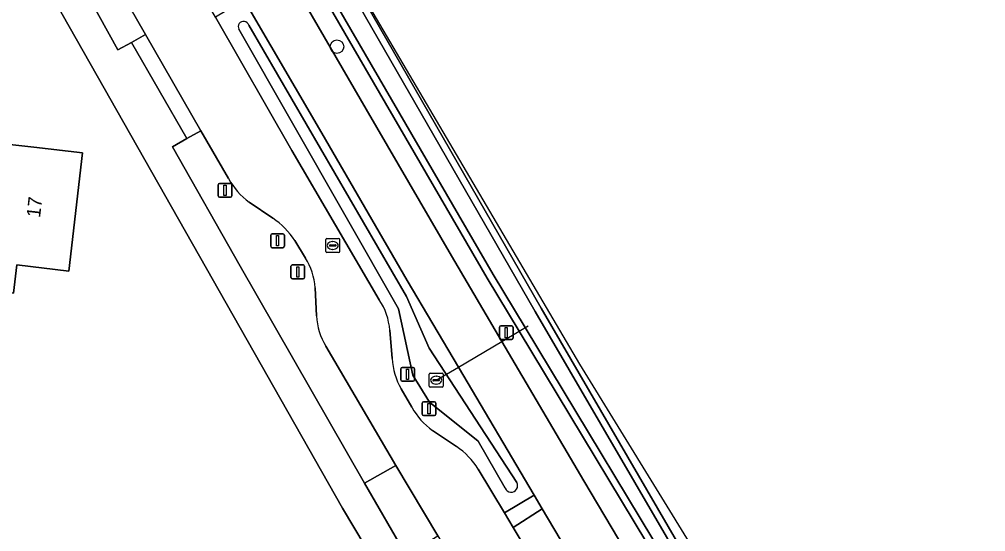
# Model space of a CAD drawing. Extents: x 162396 to 163643, y 386452 to 387406.
# Drawn here: x 163078.6 to 163148.6, y 386894 to 386931.2 of the extents above; entities that cross this region are included whole.
import ezdxf

# ---------------------------------------------------------------- set-up
doc = ezdxf.new("R2010")
doc.units = 0
for name, color, linetype in [('IMGEO_Afsluitpaal', 7, 'Continuous'), ('IMGEO_Berm_groen', 7, 'Continuous'), ('IMGEO_Boom', 7, 'Continuous'), ('IMGEO_Duiker', 7, 'Continuous'), ('IMGEO_Erf', 7, 'Continuous'), ('IMGEO_Fietspad_gesloten', 7, 'Continuous'), ('IMGEO_Fietspad_halfverhard', 7, 'Continuous'), ('IMGEO_Grasland_agrarisch', 7, 'Continuous'), ('IMGEO_Greppel_droge_sloot', 7, 'Continuous'), ('IMGEO_Hek', 7, 'Continuous'), ('IMGEO_Lichtmast', 7, 'Continuous'), ('IMGEO_Oever', 7, 'Continuous'), ('IMGEO_Pand', 7, 'Continuous'), ('IMGEO_Pand_nummerreeks', 7, 'Continuous'), ('IMGEO_Parkeervlak_halfverhard', 7, 'Continuous'), ('IMGEO_Rijbaan_lokaal_gesloten', 7, 'Continuous'), ('IMGEO_Rioolput', 7, 'Continuous'), ('IMGEO_Voetpad_open', 7, 'Continuous')]:
    doc.layers.add(name, color=color, linetype=linetype)

msp = doc.modelspace()

# ---------------------------------------------------------------- linework, layer by layer
at = {"layer": 'IMGEO_Afsluitpaal'}
for p, q in [((163096.799, 386914.692), (163096.799, 386915.492)), ((163096.799, 386915.492), (163096.799, 386914.692)), ((163096.899, 386915.592), (163097.689, 386915.592)), ((163097.689, 386915.592), (163096.899, 386915.592)), ((163097.789, 386915.492), (163097.789, 386914.692)), ((163097.789, 386914.692), (163097.789, 386915.492)), ((163097.689, 386914.592), (163096.899, 386914.592)), ((163096.899, 386914.592), (163097.689, 386914.592)), ((163098.369, 386913.338), (163099.159, 386913.338)), ((163099.159, 386913.338), (163098.369, 386913.338)), ((163098.269, 386912.438), (163098.269, 386913.238)), ((163098.269, 386913.238), (163098.269, 386912.438)), ((163099.259, 386913.238), (163099.259, 386912.438)), ((163099.259, 386912.438), (163099.259, 386913.238)), ((163099.159, 386912.338), (163098.369, 386912.338)), ((163098.369, 386912.338), (163099.159, 386912.338)), ((163106.225, 386905.008), (163106.225, 386905.808)), ((163106.225, 386905.808), (163106.225, 386905.008)), ((163106.325, 386905.908), (163107.115, 386905.908)), ((163107.115, 386905.908), (163106.325, 386905.908)), ((163107.215, 386905.808), (163107.215, 386905.008)), ((163107.215, 386905.008), (163107.215, 386905.808)), ((163107.115, 386904.908), (163106.325, 386904.908)), ((163106.325, 386904.908), (163107.115, 386904.908)), ((163107.777, 386902.512), (163107.777, 386903.312)), ((163107.777, 386903.312), (163107.777, 386902.512)), ((163107.877, 386903.412), (163108.667, 386903.412)), ((163108.667, 386903.412), (163107.877, 386903.412)), ((163108.767, 386903.312), (163108.767, 386902.512)), ((163108.767, 386902.512), (163108.767, 386903.312)), ((163108.667, 386902.412), (163107.877, 386902.412)), ((163107.877, 386902.412), (163108.667, 386902.412))]:
    msp.add_line(p, q, dxfattribs=at)
for points in [[(163097.219, 386915.467), (163097.369, 386915.467), (163097.369, 386914.717), (163097.219, 386914.717), (163097.219, 386915.467)], [(163098.689, 386913.213), (163098.839, 386913.213), (163098.839, 386912.463), (163098.689, 386912.463), (163098.689, 386913.213)], [(163106.645, 386905.783), (163106.795, 386905.783), (163106.795, 386905.033), (163106.645, 386905.033), (163106.645, 386905.783)], [(163108.197, 386903.287), (163108.347, 386903.287), (163108.347, 386902.537), (163108.197, 386902.537), (163108.197, 386903.287)]]:
    msp.add_lwpolyline(points, dxfattribs=at)
for centre, start, end in [((163096.899, 386915.492), 90, 180), ((163096.899, 386915.492), 90, 180), ((163097.689, 386915.492), 0, 90), ((163097.689, 386915.492), 360, 90), ((163096.899, 386914.692), 180, 270), ((163096.899, 386914.692), 180, 270), ((163097.689, 386914.692), 270, 0), ((163097.689, 386914.692), 270, 0), ((163098.369, 386913.238), 90, 180), ((163098.369, 386913.238), 90, 180), ((163099.159, 386913.238), 0, 90), ((163099.159, 386913.238), 360, 90), ((163098.369, 386912.438), 180, 270), ((163098.369, 386912.438), 180, 270), ((163099.159, 386912.438), 270, 0), ((163099.159, 386912.438), 270, 0), ((163106.325, 386905.808), 90, 180), ((163106.325, 386905.808), 90, 180), ((163107.115, 386905.808), 0, 90), ((163107.115, 386905.808), 360, 90), ((163106.325, 386905.008), 180, 270), ((163106.325, 386905.008), 180, 270), ((163107.115, 386905.008), 270, 0), ((163107.115, 386905.008), 270, 0), ((163107.877, 386903.312), 90, 180), ((163107.877, 386903.312), 90, 180), ((163108.667, 386903.312), 0, 90), ((163108.667, 386903.312), 360, 90), ((163107.877, 386902.512), 180, 270), ((163107.877, 386902.512), 180, 270), ((163108.667, 386902.512), 270, 0), ((163108.667, 386902.512), 270, 0)]:
    msp.add_arc(centre, 0.1, start, end, dxfattribs=at)
at = {"layer": 'IMGEO_Berm_groen'}
for points in [[(163058.321, 387013.033), (163062.245, 387003.85), (163065.679, 386996.007), (163072.387, 386981.888), (163076.252, 386973.982), (163079.946, 386966.717), (163082.017, 386962.946), (163085.197, 386957.174), (163087.753, 386952.543), (163088.198, 386951.737), (163088.644, 386950.931), (163089.035, 386950.226), (163090.045, 386948.352), (163091.713, 386945.359), (163103.715, 386924.646), (163109.912, 386913.996), (163113.552, 386907.796), (163119.49, 386897.68), (163133.047, 386874.854), (163141.068, 386861.652), (163143.895, 386857.051), (163155.065, 386838.871)], [(163153.066, 386846.995), (163145.801, 386858.335), (163140.584, 386866.478), (163126.817, 386888.603), (163114.805, 386908.538), (163112.488, 386912.383), (163096.88, 386939.306)], [(163100.492, 386922.911), (163094.886, 386932.55), (163092.789, 386931.308), (163098.32, 386921.635), (163104.671, 386910.799)], [(163113.792, 386897.146), (163111.823, 386900.546), (163108.303, 386903.381), (163107.11, 386905.349), (163106.066, 386910.153), (163094.49, 386930.439)], [(163095.206, 386930.737), (163106.632, 386911.047), (163108.273, 386907.289), (163114.627, 386897.563)], [(163091.734, 386923.078), (163090.714, 386922.504), (163089.68, 386921.904), (163094.586, 386913.257), (163103.597, 386897.495), (163105.855, 386898.787), (163100.8, 386907.449)], [(163093.731, 386919.599), (163091.734, 386923.078)], [(163111.839, 386898.512), (163113.745, 386895.358), (163115.894, 386896.629), (163110.406, 386905.934), (163106.699, 386912.218), (163100.492, 386922.911)], [(163096.944, 386916.735), (163095.24, 386917.884)], [(163099.312, 386913.838), (163098.54, 386915.109)], [(163100.117, 386909.636), (163100.03, 386911.687)], [(163105.438, 386908.608), (163105.611, 386906.545)], [(163106.246, 386904.35), (163107.019, 386903.009)], [(163108.535, 386901.325), (163110.255, 386900.168)]]:
    msp.add_lwpolyline(points, dxfattribs=at)
for points in [[(163084.761, 386935.248), (163082.833, 386934.162), (163085.725, 386928.948), (163086.703, 386929.474), (163087.725, 386930.063)], [(163116.481, 386895.637), (163114.367, 386894.296), (163127.83, 386871.73), (163134.797, 386860.218), (163136.893, 386861.494), (163129.911, 386872.986)]]:
    msp.add_lwpolyline(points, close=True, dxfattribs=at)
for centre, radius, start, end in [((163094.834, 386930.621), 0.389, 17.32456, 207.8697), ((163098.71, 386922.459), 5.742, 209.87088, 232.81715), ((163094.064, 386912.312), 5.278, 32.00171, 56.93136), ((163095.268, 386911.293), 4.779, 4.73337, 32.18447), ((163100.627, 386908.154), 4.832, 5.39554, 33.19154), ((163104.77, 386909.889), 4.66, 183.11311, 211.57406), ((163110.677, 386906.821), 5.073, 183.12072, 209.14895), ((163111.657, 386905.66), 5.342, 209.75077, 234.23869), ((163107.412, 386895.863), 5.159, 30.89421, 56.55973), ((163114.227, 386897.32), 0.468, 201.78194, 31.29325)]:
    msp.add_arc(centre, radius, start, end, dxfattribs=at)
at = {"layer": 'IMGEO_Boom'}
msp.add_circle((163101.599, 386929.174), 0.489, dxfattribs=at)
at = {"layer": 'IMGEO_Duiker'}
msp.add_lwpolyline([(163108.792, 386904.978), (163110.406, 386905.934), (163113.552, 386907.796), (163114.805, 386908.538), (163115.453, 386908.922)], dxfattribs=at)
at = {"layer": 'IMGEO_Erf'}
msp.add_lwpolyline([(163143.068, 386827.803), (163123.585, 386859.49), (163102.006, 386895.698), (163079.761, 386934.958), (163074.122, 386945.175)], dxfattribs=at)
msp.add_lwpolyline([(163066.997, 386929.103), (163070.741, 386928.672), (163075.708, 386928.1), (163075.247, 386924.097), (163075.052, 386922.399), (163079.622, 386921.873), (163083.162, 386921.466), (163082.176, 386912.899), (163078.39, 386913.335), (163078.154, 386911.287), (163073.187, 386911.859), (163069.581, 386912.274), (163070.781, 386922.707), (163066.32, 386923.22)], close=True, dxfattribs=at)
at = {"layer": 'IMGEO_Fietspad_gesloten'}
for points in [[(163155.065, 386838.871), (163143.895, 386857.051), (163141.068, 386861.652), (163133.047, 386874.854), (163119.49, 386897.68), (163113.552, 386907.796), (163109.912, 386913.996), (163103.715, 386924.646), (163091.713, 386945.359), (163090.045, 386948.352), (163089.035, 386950.226), (163088.644, 386950.931), (163088.198, 386951.737), (163087.753, 386952.543), (163085.197, 386957.174), (163082.017, 386962.946), (163079.946, 386966.717), (163076.252, 386973.982), (163072.387, 386981.888), (163065.679, 386996.007), (163062.245, 387003.85), (163058.321, 387013.033)], [(163081.061, 386957.239), (163084.489, 386950.829), (163086.516, 386947.047), (163094.302, 386933.576), (163094.886, 386932.55), (163100.492, 386922.911), (163106.699, 386912.218), (163110.406, 386905.934), (163115.894, 386896.629), (163116.481, 386895.637), (163129.911, 386872.986), (163136.893, 386861.494), (163137.525, 386860.5), (163140.88, 386855.017), (163151.706, 386837.322), (163156.522, 386829.586)]]:
    msp.add_lwpolyline(points, dxfattribs=at)
at = {"layer": 'IMGEO_Fietspad_halfverhard'}
msp.add_lwpolyline([(163116.481, 386895.637), (163115.894, 386896.629), (163113.745, 386895.358), (163114.367, 386894.296)], close=True, dxfattribs=at)
at = {"layer": 'IMGEO_Grasland_agrarisch'}
msp.add_lwpolyline([(163098.137, 386941.992), (163116.399, 386910.212), (163128.365, 386889.63), (163142.301, 386867.412), (163154.565, 386848.11), (163157.583, 386842.961), (163157.905, 386843.143), (163162.006, 386845.923), (163174.171, 386826.377), (163170.355, 386823.925), (163171.995, 386820.854), (163236.272, 386723.927)], dxfattribs=at)
at = {"layer": 'IMGEO_Greppel_droge_sloot'}
for points in [[(163097.315, 386939.553), (163112.918, 386912.637), (163115.235, 386908.793), (163127.243, 386888.864), (163141.007, 386866.745), (163146.215, 386858.615), (163153.49, 386847.26), (163159.708, 386837.054), (163160.184, 386837.158), (163160.318, 386837.307), (163157.295, 386842.465), (163157.152, 386842.708), (163154.138, 386847.849), (163141.878, 386867.145), (163127.937, 386889.371), (163115.966, 386909.962), (163097.705, 386941.74)], [(163094.49, 386930.439), (163106.066, 386910.153), (163107.11, 386905.349), (163108.303, 386903.381), (163111.823, 386900.546), (163113.792, 386897.146)], [(163108.273, 386907.289), (163106.632, 386911.047), (163095.206, 386930.737)], [(163114.627, 386897.563), (163108.273, 386907.289)]]:
    msp.add_lwpolyline(points, dxfattribs=at)
for centre, radius, start, end in [((163094.834, 386930.621), 0.389, 17.32456, 207.8697), ((163114.227, 386897.32), 0.468, 201.78194, 31.29325)]:
    msp.add_arc(centre, radius, start, end, dxfattribs=at)
at = {"layer": 'IMGEO_Hek'}
for points in [[(163119.211, 386906.146), (163099.887, 386939.051), (163083.129, 386969.417), (163073.808, 386988.989), (163068.186, 387000), (163054.818, 387033.276)], [(163157.905, 386843.143), (163119.211, 386906.146)]]:
    msp.add_lwpolyline(points, dxfattribs=at)
at = {"layer": 'IMGEO_Lichtmast'}
for p, q in [((163092.991, 386918.346), (163092.991, 386919.146)), ((163092.991, 386919.146), (163092.991, 386918.346)), ((163093.091, 386919.246), (163093.881, 386919.246)), ((163093.881, 386919.246), (163093.091, 386919.246)), ((163093.981, 386919.146), (163093.981, 386918.346)), ((163093.981, 386918.346), (163093.981, 386919.146)), ((163093.881, 386918.246), (163093.091, 386918.246)), ((163093.091, 386918.246), (163093.881, 386918.246)), ((163113.373, 386908.023), (163113.373, 386908.823)), ((163113.373, 386908.823), (163113.373, 386908.023)), ((163113.473, 386908.923), (163114.263, 386908.923)), ((163114.263, 386908.923), (163113.473, 386908.923)), ((163114.363, 386908.823), (163114.363, 386908.023)), ((163114.363, 386908.023), (163114.363, 386908.823)), ((163114.263, 386907.923), (163113.473, 386907.923)), ((163113.473, 386907.923), (163114.263, 386907.923))]:
    msp.add_line(p, q, dxfattribs=at)
for points in [[(163093.411, 386919.121), (163093.561, 386919.121), (163093.561, 386918.371), (163093.411, 386918.371), (163093.411, 386919.121)], [(163113.793, 386908.798), (163113.943, 386908.798), (163113.943, 386908.048), (163113.793, 386908.048), (163113.793, 386908.798)]]:
    msp.add_lwpolyline(points, dxfattribs=at)
for centre, start, end in [((163093.091, 386919.146), 90, 180), ((163093.091, 386919.146), 90, 180), ((163093.881, 386919.146), 0, 90), ((163093.881, 386919.146), 360, 90), ((163093.091, 386918.346), 180, 270), ((163093.091, 386918.346), 180, 270), ((163093.881, 386918.346), 270, 0), ((163093.881, 386918.346), 270, 0), ((163113.473, 386908.823), 90, 180), ((163113.473, 386908.823), 90, 180), ((163114.263, 386908.823), 0, 90), ((163114.263, 386908.823), 360, 90), ((163113.473, 386908.023), 180, 270), ((163113.473, 386908.023), 180, 270), ((163114.263, 386908.023), 270, 0), ((163114.263, 386908.023), 270, 0)]:
    msp.add_arc(centre, 0.1, start, end, dxfattribs=at)
at = {"layer": 'IMGEO_Oever'}
for points in [[(163089.008, 386953.161), (163092.32, 386947.094), (163093.973, 386944.513), (163096.88, 386939.306), (163112.488, 386912.383), (163114.805, 386908.538), (163126.817, 386888.603), (163140.584, 386866.478), (163145.801, 386858.335), (163153.066, 386846.995), (163159.466, 386836.49), (163160.448, 386836.704), (163160.934, 386837.244), (163157.726, 386842.718), (163157.583, 386842.961), (163154.565, 386848.11), (163142.301, 386867.412), (163128.365, 386889.63), (163116.399, 386910.212), (163098.137, 386941.992)], [(163097.705, 386941.74), (163115.966, 386909.962), (163127.937, 386889.371), (163141.878, 386867.145), (163154.138, 386847.849), (163157.152, 386842.708), (163157.295, 386842.465), (163160.318, 386837.307), (163160.184, 386837.158), (163159.708, 386837.054), (163153.49, 386847.26), (163146.215, 386858.615), (163141.007, 386866.745), (163127.243, 386888.864), (163115.235, 386908.793), (163112.918, 386912.637), (163097.315, 386939.553)]]:
    msp.add_lwpolyline(points, dxfattribs=at)
at = {"layer": 'IMGEO_Pand'}
msp.add_lwpolyline([(163078.154, 386911.287), (163078.39, 386913.335), (163082.176, 386912.899), (163083.162, 386921.466), (163079.622, 386921.873), (163075.052, 386922.399), (163075.247, 386924.097), (163075.708, 386928.1), (163070.741, 386928.672), (163066.997, 386929.103), (163066.32, 386923.22), (163070.781, 386922.707), (163069.581, 386912.274), (163073.187, 386911.859)], close=True, dxfattribs=at)
at = {"layer": 'IMGEO_Parkeervlak_halfverhard'}
msp.add_lwpolyline([(163105.855, 386898.787), (163103.597, 386897.495), (163106.622, 386892.28), (163107.915, 386893.07), (163108.904, 386893.677)], close=True, dxfattribs=at)
at = {"layer": 'IMGEO_Rijbaan_lokaal_gesloten'}
for points in [[(163066.861, 386968.103), (163069.593, 386962.768), (163072.362, 386957.447), (163077.829, 386947.291), (163078.261, 386946.568), (163084.761, 386935.248), (163087.725, 386930.063), (163091.734, 386923.078), (163093.731, 386919.599)], [(163104.671, 386910.799), (163098.32, 386921.635), (163092.789, 386931.308), (163092.196, 386932.358), (163089.079, 386937.755), (163083.226, 386947.963), (163082.278, 386949.631)], [(163095.24, 386917.884), (163096.944, 386916.735)], [(163098.54, 386915.109), (163099.312, 386913.838)], [(163100.03, 386911.687), (163100.117, 386909.636)], [(163105.611, 386906.545), (163105.438, 386908.608)], [(163100.8, 386907.449), (163105.855, 386898.787), (163108.904, 386893.677), (163112.007, 386888.479), (163120.994, 386873.425), (163126.92, 386863.539), (163130.045, 386858.445), (163133.171, 386853.318), (163140.649, 386841.134), (163147.359, 386830.262)], [(163107.019, 386903.009), (163106.246, 386904.35)], [(163110.255, 386900.168), (163108.535, 386901.325)], [(163152.596, 386831.287), (163135.447, 386859.2), (163134.797, 386860.218), (163127.83, 386871.73), (163114.367, 386894.296), (163113.745, 386895.358), (163111.839, 386898.512)]]:
    msp.add_lwpolyline(points, dxfattribs=at)
for centre, radius, start, end in [((163098.71, 386922.459), 5.742, 209.87088, 232.81715), ((163094.064, 386912.312), 5.278, 32.00171, 56.93136), ((163095.268, 386911.293), 4.779, 4.73337, 32.18447), ((163100.627, 386908.154), 4.832, 5.39554, 33.19154), ((163104.77, 386909.889), 4.66, 183.11311, 211.57406), ((163110.677, 386906.821), 5.073, 183.12072, 209.14895), ((163111.657, 386905.66), 5.342, 209.75077, 234.23869), ((163107.412, 386895.863), 5.159, 30.89421, 56.55973)]:
    msp.add_arc(centre, radius, start, end, dxfattribs=at)
at = {"layer": 'IMGEO_Rioolput'}
for p, q in [((163100.795, 386914.322), (163100.795, 386915.174)), ((163100.87, 386915.248), (163101.722, 386915.248)), ((163101.054, 386914.742), (163101.054, 386914.754)), ((163101.492, 386914.705), (163101.094, 386914.705)), ((163101.097, 386914.791), (163101.495, 386914.791)), ((163101.283, 386915.028), (163101.308, 386915.028)), ((163101.538, 386914.754), (163101.538, 386914.742)), ((163101.796, 386915.174), (163101.796, 386914.322)), ((163101.722, 386914.248), (163100.87, 386914.248)), ((163101.306, 386914.468), (163101.281, 386914.468)), ((163108.291, 386904.552), (163108.291, 386905.404)), ((163108.366, 386905.478), (163109.218, 386905.478)), ((163108.55, 386904.972), (163108.55, 386904.984)), ((163108.988, 386904.935), (163108.59, 386904.935)), ((163108.593, 386905.021), (163108.991, 386905.021)), ((163108.779, 386905.258), (163108.804, 386905.258)), ((163109.034, 386904.984), (163109.034, 386904.972)), ((163109.292, 386905.404), (163109.292, 386904.552)), ((163109.218, 386904.478), (163108.366, 386904.478)), ((163108.802, 386904.698), (163108.777, 386904.698))]:
    msp.add_line(p, q, dxfattribs=at)
for points in [[(163100.795, 386914.322), (163100.795, 386915.174)], [(163100.87, 386915.248), (163101.722, 386915.248)], [(163101.796, 386915.174), (163101.796, 386914.322)], [(163101.722, 386914.248), (163100.87, 386914.248)], [(163108.291, 386904.552), (163108.291, 386905.404)], [(163108.366, 386905.478), (163109.218, 386905.478)], [(163109.292, 386905.404), (163109.292, 386904.552)], [(163109.218, 386904.478), (163108.366, 386904.478)]]:
    msp.add_lwpolyline(points, dxfattribs=at)
for centre, radius, start, end in [((163100.872, 386915.172), 0.0765, 91.55205, 178.44795), ((163100.872, 386915.172), 0.0765, 91.55205, 178.44795), ((163101.094, 386914.751), 0.0403, 85.87752, 175.75265), ((163101.091, 386914.741), 0.0366, 178.93798, 274.71019), ((163101.495, 386914.748), 0.043, 264.86636, 352.45326), ((163101.499, 386914.753), 0.0386, 1.73085, 96.63898), ((163101.72, 386915.172), 0.0765, 1.55205, 88.44795), ((163101.72, 386915.172), 0.0765, 1.55205, 88.44795), ((163100.872, 386914.324), 0.0765, 181.55205, 268.44795), ((163100.872, 386914.324), 0.0765, 181.55205, 268.44795), ((163101.72, 386914.324), 0.0765, 271.55205, 358.44795), ((163101.72, 386914.324), 0.0765, 271.55205, 358.44795), ((163108.368, 386905.402), 0.0765, 91.55205, 178.44795), ((163108.368, 386905.402), 0.0765, 91.55205, 178.44795), ((163108.59, 386904.981), 0.0403, 85.87752, 175.75265), ((163108.587, 386904.971), 0.0366, 178.93798, 274.71019), ((163108.991, 386904.978), 0.043, 264.86636, 352.45326), ((163108.995, 386904.983), 0.0386, 1.73085, 96.63898), ((163109.216, 386905.402), 0.0765, 1.55205, 88.44795), ((163109.216, 386905.402), 0.0765, 1.55205, 88.44795), ((163108.368, 386904.554), 0.0765, 181.55205, 268.44795), ((163108.368, 386904.554), 0.0765, 181.55205, 268.44795), ((163109.216, 386904.554), 0.0765, 271.55205, 358.44795), ((163109.216, 386904.554), 0.0765, 271.55205, 358.44795)]:
    msp.add_arc(centre, radius, start, end, dxfattribs=at)
for centre, major_axis, ratio, start_param, end_param in [((163101.282, 386914.748), (-0.387, 0.002), 0.722429, 4.712389, 7.853982), ((163101.307, 386914.748), (-0.39, 0.002), 0.717154, 1.570796, 4.712389), ((163108.778, 386904.978), (-0.387, 0.002), 0.722429, 4.712389, 7.853982), ((163108.803, 386904.978), (-0.39, 0.002), 0.717154, 1.570796, 4.712389)]:
    msp.add_ellipse(centre, major_axis=major_axis, ratio=ratio, start_param=start_param, end_param=end_param, dxfattribs=at)
at = {"layer": 'IMGEO_Voetpad_open'}
for points in [[(163016.462, 387091.359), (163024.497, 387061.137), (163030.729, 387041.536), (163041.387, 387012.856), (163042.57, 387009.785), (163046.866, 387000), (163053.248, 386986.028), (163057.319, 386977.598), (163067.344, 386957.823), (163074.122, 386945.175), (163079.761, 386934.958), (163102.006, 386895.698), (163123.585, 386859.49), (163143.068, 386827.803)], [(163148.158, 386827.738), (163146.104, 386827.388), (163138.449, 386839.645), (163130.798, 386851.848), (163132.152, 386852.695), (163129.05, 386857.843), (163127.647, 386856.97), (163124.5, 386862.121), (163118.528, 386872), (163109.622, 386887.031), (163110.973, 386887.848), (163107.915, 386893.07), (163106.622, 386892.28), (163103.597, 386897.495), (163094.586, 386913.257), (163089.68, 386921.904), (163090.714, 386922.504), (163086.703, 386929.474), (163085.725, 386928.948), (163082.833, 386934.162), (163075.976, 386946.453)]]:
    msp.add_lwpolyline(points, dxfattribs=at)
msp.add_lwpolyline([(163087.725, 386930.063), (163086.703, 386929.474), (163090.714, 386922.504), (163091.734, 386923.078)], close=True, dxfattribs=at)

# ---------------------------------------------------------------- texts
at = {"layer": 'IMGEO_Pand_nummerreeks'}
msp.add_text('17', height=1, rotation=83.43456, dxfattribs=at).set_placement((163080.081, 386916.74))

doc.saveas('drawing.dxf')
